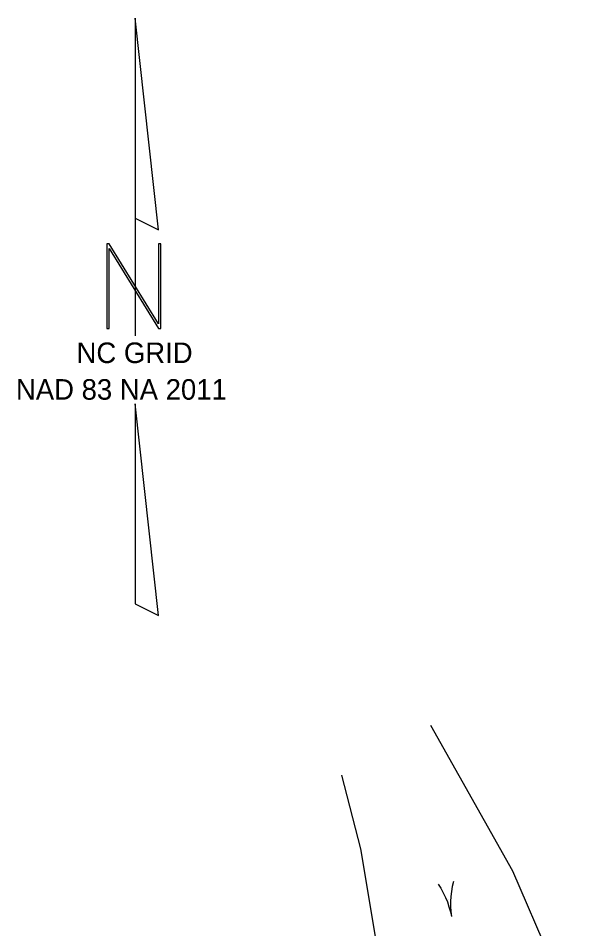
# Model space of a CAD drawing. Extents: x 2225821 to 2228892, y 553570 to 558465.
# Drawn here: x 2226803.6 to 2226965.5, y 556456.6 to 556722.3 of the extents above; entities that cross this region are included whole.
import ezdxf

# ---------------------------------------------------------------- set-up
doc = ezdxf.new("R2010")
doc.units = 0
for name, color, linetype in [('CTL North Arrow NAD 83 NA 2011 CELL', 7, 'Continuous'), ('Exist Hydro Stream Flow Arrow CELL', 7, 'Continuous'), ('Exist Hydro Stream or Body of Water', 7, 'Continuous')]:
    doc.layers.add(name, color=color, linetype=linetype)

msp = doc.modelspace()

# ---------------------------------------------------------------- linework, layer by layer
at = {"layer": 'CTL North Arrow NAD 83 NA 2011 CELL'}
msp.add_line((2226837.9, 556635.04), (2226837.9, 556635.04), dxfattribs=at)
for points in [[(2226837.75, 556722.33), (2226837.75, 556664), (2226844.63, 556660.56)], [(2226829.53, 556631.78), (2226830.21, 556631.78), (2226830.21, 556655.1), (2226844.63, 556631.78), (2226845.31, 556631.78), (2226845.31, 556656.46), (2226844.63, 556656.46), (2226844.63, 556633.14), (2226830.21, 556656.46), (2226829.53, 556656.46)], [(2226837.75, 556551.49), (2226844.63, 556548.08), (2226837.75, 556609.81)]]:
    msp.add_lwpolyline(points, close=True, dxfattribs=at)
msp.add_lwpolyline([(2226837.75, 556664), (2226837.75, 556629.7)], dxfattribs=at)
at = {"layer": 'Exist Hydro Stream Flow Arrow CELL'}
msp.add_line((2226929.26, 556465.14), (2226929.26, 556465.14), dxfattribs=at)
for points in [[(2226930.68, 556470.45), (2226930.31, 556469.03), (2226930.09, 556467.55), (2226929.9, 556466.08), (2226929.82, 556464.64), (2226929.83, 556463.15), (2226929.92, 556461.66), (2226930.09, 556460.21)], [(2226926.17, 556469.68), (2226926.98, 556468.46), (2226927.68, 556467.14), (2226928.34, 556465.82), (2226928.89, 556464.48), (2226929.36, 556463.07), (2226929.77, 556461.63), (2226930.09, 556460.21)]]:
    msp.add_lwpolyline(points, dxfattribs=at)
at = {"layer": 'Exist Hydro Stream or Body of Water'}
for points in [[(2226963.62, 556374.18), (2226965.5, 556386.04), (2226963.96, 556397.18), (2226959.22, 556423.11), (2226959, 556448.01), (2226947.97, 556473.42), (2226924.1, 556515.93)], [(2226921.88, 556376.33), (2226916.75, 556401.38), (2226920.33, 556422.95), (2226909.85, 556442.7), (2226903.61, 556480.01), (2226898.14, 556501.43)]]:
    msp.add_lwpolyline(points, dxfattribs=at)

# ---------------------------------------------------------------- texts
at = {"layer": 'CTL North Arrow NAD 83 NA 2011 CELL'}
for s, p in [('NC GRID', (2226820.67, 556621.71)), ('NAD 83 NA 2011', (2226802.98, 556611.02))]:
    msp.add_text(s, height=6, dxfattribs=at).set_placement(p)

doc.saveas('drawing.dxf')
